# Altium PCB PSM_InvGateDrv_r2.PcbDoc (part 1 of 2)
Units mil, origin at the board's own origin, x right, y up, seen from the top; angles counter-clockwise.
Board outline 5413.39 x 2000 mil, 2 copper layers (Top Layer, Bottom Layer), stack 62 mil thick; 132 components, 58 nets, 317 pads, 172 vias.
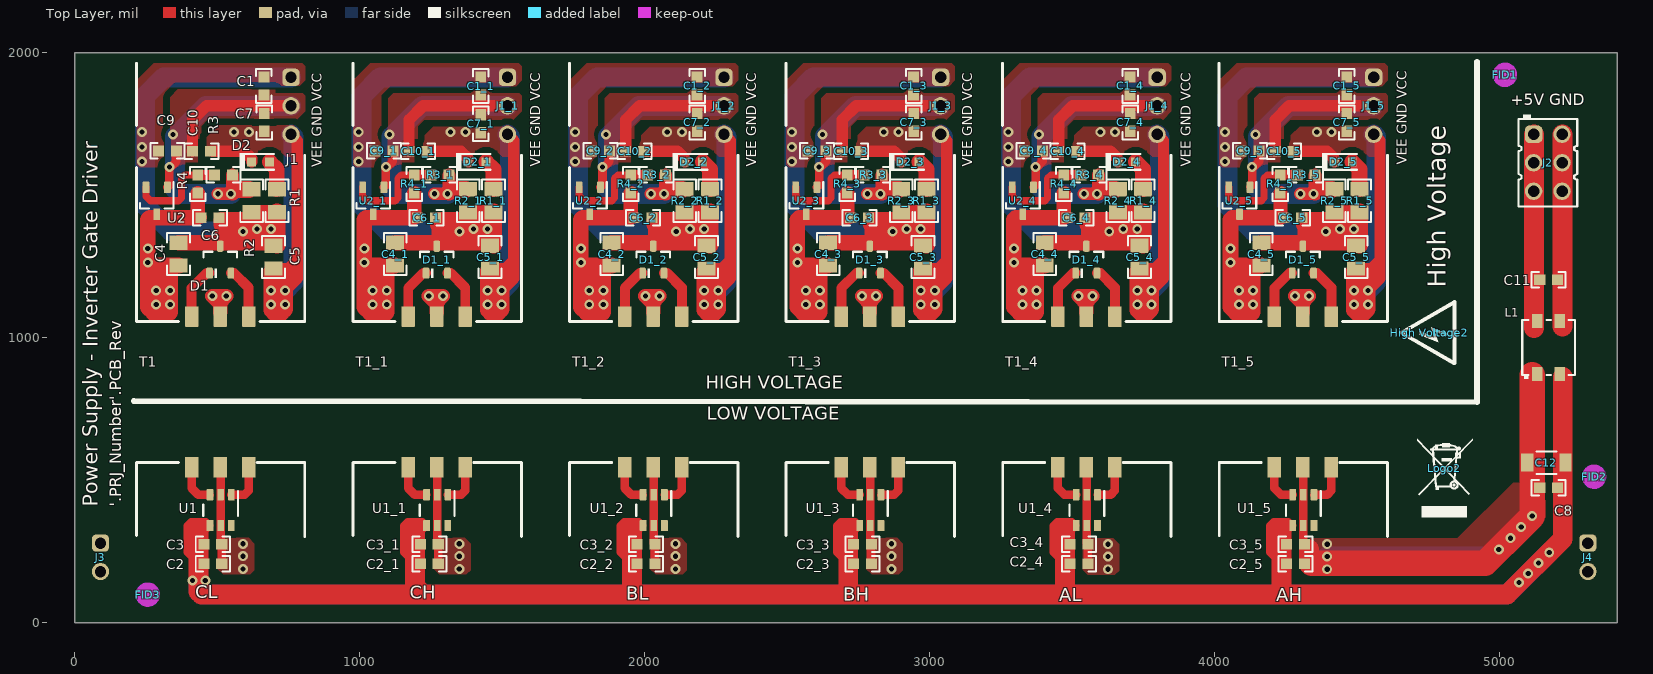
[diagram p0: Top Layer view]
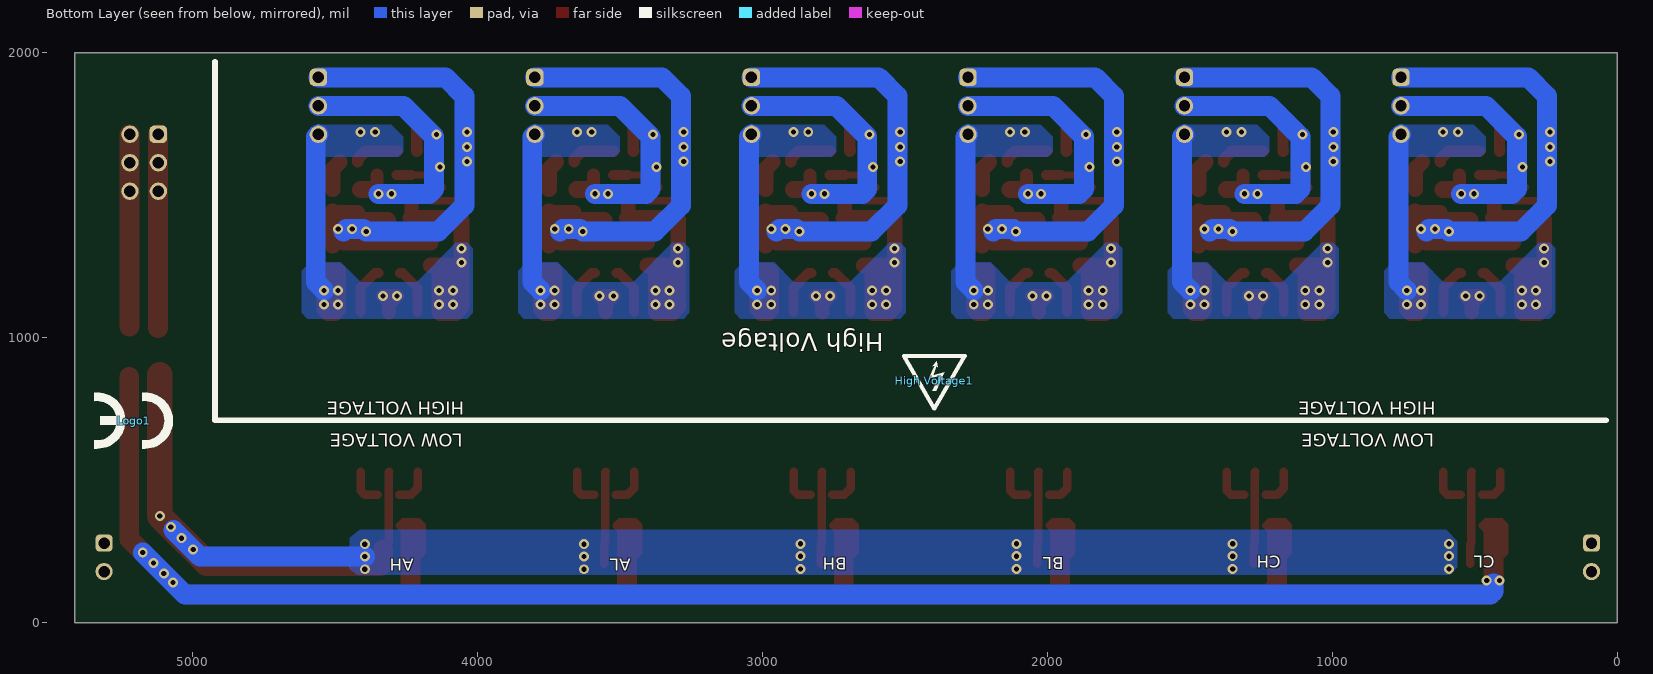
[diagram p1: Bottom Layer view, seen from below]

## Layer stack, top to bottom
Top Solder: solder mask 0.4, Solder Resist, Dk 3.5
Top Layer: signal copper 1.4
Dielectric1: core 59.2, FR-4, Dk 4.8
Bottom Layer: signal copper 1.4
Bottom Solder: solder mask 0.4, Solder Resist, Dk 3.5

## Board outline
0,0 5413.39,0 5413.39,2000 0,2000

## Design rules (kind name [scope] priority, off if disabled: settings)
AcuteAngle [All] p1: minimum=4.50000000000000E+0001 checktracksonly=FALSE
AssemblyTestPointUsage [All] p1: valid=2
BoardOutlineClearance BoardOutlineClearance_MountingHoles [OnCopper and InComponentClass('Mounting Holes')] p1: gap=20 ignorepadtopadclearanceinfootprint=FALSE
BoardOutlineClearance BoardOutlineClearance_Poly [OnCopper and IsPoly] p2: gap=25 ignorepadtopadclearanceinfootprint=FALSE
BoardOutlineClearance [OnCopper and Not InComponentClass('Logo') and not InComponentClass('FiducialMark') and not InRegion(1000,500,4000,800) and not InPoly] p3: gap=20 ignorepadtopadclearanceinfootprint=FALSE
Clearance Clearance_Keepouts [((IsTrack Or IsArc) And Not InPoly) And IsFree and IsKeepOut vs ((IsTrack Or IsArc) And Not InPoly) And IsFree and IsKeepOut] p1: gap=0 ignorepadtopadclearanceinfootprint=FALSE
Clearance Clearance_Poly [InPolygon] p2: gap=25 ignorepadtopadclearanceinfootprint=TRUE
Clearance Clearance_FiducialMark [IsKeepOut and InComponentClass('FiducialMark') vs IsPad and InComponentClass('FiducialMark')] p3: gap=0 ignorepadtopadclearanceinfootprint=FALSE
Clearance [All] p4: gap=7.87 ignorepadtopadclearanceinfootprint=TRUE
ComponentClearance ComponentClearance_MountingHoles_FiducialMarks [InComponentClass('Mounting Holes') vs InComponentClass('FiducialMark')] p1: gap=50 collisioncheckmode=3 verticalgap=10 showdistances=FALSE
ComponentClearance ComponentClearance_Shunt [InComponentClass('Header') vs InComponentClass('Shunt')] p2: gap=0 collisioncheckmode=3 verticalgap=0 showdistances=FALSE
ComponentClearance ComponentClearance_Logo [InComponentClass('Logo')] p3: gap=50 collisioncheckmode=3 verticalgap=10 showdistances=FALSE
ComponentClearance ComponentClearance_ScrewToNut [(HasFootprint('NY PMS 440 0025 PH')) vs (HasFootprint('Keystone_1902C'))] p4: gap=5 collisioncheckmode=3 verticalgap=10 showdistances=FALSE
ComponentClearance ComponentClearance_MountingHoles [InComponentClass('Mounting Holes')] p5: gap=250 collisioncheckmode=3 verticalgap=100000 showdistances=FALSE
ComponentClearance ComponentClearance_SmallPassives [HasFootprint('0201*') or HasFootprint('0402*') or HasFootprint('0508') or HasFootprint('0603*') or HasFootprint('0612') or HasFootprint('0805*') or HasFootprint('0815*') or HasFootprint('0830*') or HasFootprint('1206*') or HasFootprint('1210*') or HasFootprint('1808*') or HasFootprint('1812*') or HasFootprint('1825*') or HasFootprint('2010*') or HasFootprint('2220*') or HasFootprint('2225*') or HasFootprint('2512*') or HasFootprint('2728*') or HasFootprint('3518*') vs HasFootprint('0201*') or HasFootprint('0402*') or HasFootprint('0508') or HasFootprint('0603*') or HasFootprint('0612') or HasFootprint('0805*') or HasFootprint('0815*') or HasFootprint('0830*') or HasFootprint('1206*') or HasFootprint('1210*') or HasFootprint('1808*') or HasFootprint('1812*') or HasFootprint('1825*') or HasFootprint('2010*') or HasFootprint('2220*') or HasFootprint('2225*') or HasFootprint('2512*') or HasFootprint('2728*') or HasFootprint('3518*')] p6: gap=14.96 collisioncheckmode=3 verticalgap=10 showdistances=FALSE
ComponentClearance ComponentClearance_THtoSMT [IsThruComponent vs IsSMTComponent] p7: gap=25 collisioncheckmode=3 verticalgap=30 showdistances=FALSE
ComponentClearance ComponentClearance_THtoTH [IsThruComponent vs IsThruComponent] p8: gap=30 collisioncheckmode=3 verticalgap=30 showdistances=FALSE
ComponentClearance [All] p9: gap=30 collisioncheckmode=3 verticalgap=10 showdistances=FALSE
DiffPairsRouting [All] p1: maxlimit=100 minlimit=10 mostfreqgap=10 toplayer_minwidth=15 toplayer_maxwidth=15 toplayer_prefwidth=15 bottomlayer_minwidth=15 bottomlayer_maxwidth=15 bottomlayer_prefwidth=15 maxuncoupledlength=1000
FabricationTestPointUsage TestPointUsage [All] p1: valid=2 allowmultiple=FALSE
FabricationTestpoint Testpoint [All] p1: side=3 testpointundercomponent=TRUE minsize=40 maxsize=100 preferedsize=60 minholesize=0 maxholesize=40 preferedholesize=32 testpointgrid=1 allowsidetop=TRUE allowsidebottom=TRUE usegrid=TRUE gridtolerance=0.01
FanoutControl Fanout_LCC [IsLCC] p1: bgadir=Out bgaviamode=Centered fanoutstyle=Auto fanoutdirection=Alternating viagrid=1 // Fanout_LCC (Default Rule)
FanoutControl Fanout_BGA [IsBGA] p2: bgadir=Out bgaviamode=Centered fanoutstyle=Auto fanoutdirection=Alternating viagrid=1 // Fanout_BGA (Default Rule)
FanoutControl Fanout_Default [All] p4: bgadir=Out bgaviamode=Centered fanoutstyle=Auto fanoutdirection=Alternating viagrid=1 // Fanout_Default (Default Rule)
FanoutControl Fanout_Small [(CompPinCount < 5)] p5: bgadir=Out bgaviamode=Centered fanoutstyle=Auto fanoutdirection=OutThenIn viagrid=1 // Fanout_Small (Default Rule)
HoleSize [All] p1: absolutevalues=TRUE maxlimit=251 minlimit=7.87 maxpercent=80.000 minpercent=20.000
MinimumAnnularRing MinimumAnnularRing_ThermalPadVias [IsVia and InAnyComponent] p1: minimumring=5.91
MinimumAnnularRing [All] p2: minimumring=7.87
MinimumSolderMaskSliver MinimumSolderMaskSliver_Logo [InComponentClass('Logo') vs InComponentClass('Logo')] p1: minsoldermaskwidth=0.7
MinimumSolderMaskSliver [All] p2: minsoldermaskwidth=3.94
PlaneConnect [All] p1: planeconnectstyle=Relief reliefexpansion=10 reliefentries=4 reliefconductorwidth=10 reliefairgap=10
PolygonConnect [All] p1: connectstyle=Direct reliefconductorwidth=10 reliefentries=4 polygonreliefangle="90 Angle" airgapwidth=10
RoomDefinition "Bias Supply_4" [InComponentClass('Bias Supply')] p1: confinementstyle=ConfineIn formatcopy=TRUE lockcomponents=FALSE outline 4615.87,368.9 4615.87,1765.5 4015.87,1765.5 4015.87,368.9
RoomDefinition "Bias Supply_3" [InComponentClass('Bias Supply')] p2: confinementstyle=ConfineIn formatcopy=TRUE lockcomponents=FALSE outline 3855.87,368.9 3855.87,1765.5 3255.87,1765.5 3255.87,368.9
RoomDefinition PSM_InvGateDrv [InComponentClass('PSM_InvGateDrv')] p3: confinementstyle=ConfineIn formatcopy=TRUE lockcomponents=FALSE outline 3095.87,368.9 3095.87,1765.5 2495.87,1765.5 2495.87,368.9
RoomDefinition "Bias Supply_1" [InComponentClass('Bias Supply')] p4: confinementstyle=ConfineIn formatcopy=TRUE lockcomponents=FALSE outline 2335.87,368.9 2335.87,1765.5 1735.87,1765.5 1735.87,368.9
RoomDefinition 1 [InComponentClass('1')] p5: confinementstyle=ConfineIn formatcopy=TRUE lockcomponents=FALSE outline 4615.87,368.9 4615.87,1765.5 4015.87,1765.5 4015.87,368.9
RoomDefinition 2 [InComponentClass('2')] p6: confinementstyle=ConfineIn formatcopy=TRUE lockcomponents=FALSE outline 3855.87,368.9 3855.87,1765.5 3255.87,1765.5 3255.87,368.9
RoomDefinition 3 [InComponentClass('3')] p7: confinementstyle=ConfineIn formatcopy=TRUE lockcomponents=FALSE outline 3095.87,368.9 3095.87,1765.5 2495.87,1765.5 2495.87,368.9
RoomDefinition "Stark Gate Driver_1" [InComponentClass('Stark Gate Driver_1')] p8: confinementstyle=ConfineIn formatcopy=TRUE lockcomponents=FALSE outline 2335.87,368.9 2335.87,1765.5 1735.87,1765.5 1735.87,368.9
RoomDefinition "Bias Supply" [InComponentClass('Bias Supply')] p9: confinementstyle=ConfineIn formatcopy=TRUE lockcomponents=FALSE outline 815.87,368.9 815.87,1949.29 215.87,1949.29 215.87,368.9
RoomDefinition 5 [InComponentClass('5')] p10: confinementstyle=ConfineIn formatcopy=TRUE lockcomponents=FALSE outline 1575.87,368.9 1575.87,1765.5 975.87,1765.5 975.87,368.9
RoutingVias ThermalPadVias [IsVia and InAnyComponent] p1: holewidth=7.87 width=19.68 viastyle="Through Hole" minholewidth=7.87 minwidth=19.68 maxholewidth=12.99 maxwidth=23.62
RoutingVias [All] p2: holewidth=16 width=34 viastyle="Through Hole" minholewidth=7.87 minwidth=26 maxholewidth=40 maxwidth=65
SilkToBoardRegionClearance [Not ((IsComment or IsDesignator) And (Hide <> 'False')) and not InRegion(1000,500,4000,800)] p1:
SilkToSilkClearance SilkToSilkClearance_Pb-FreeLogo [(HasFootprint('Pb-Free_Overlay_Medium') OR HasFootprint('Pb-Free_Overlay_Small')) vs (HasFootprint('Pb-Free_Overlay_Medium') OR HasFootprint('Pb-Free_Overlay_Small'))] p1: silktosilkclearance=0
SilkToSilkClearance [All] p2: silktosilkclearance=2
SilkToSolderMaskClearance SilkToComponentPadClearance [(IsPad or IsFill or IsRegion) and InAnycomponent] p1: minsilkscreentomaskgap=0 clearancetoexposedcopper=TRUE
SilkToSolderMaskClearance "Silk to Solder Mask Opening" [All] p2: minsilkscreentomaskgap=1 clearancetoexposedcopper=FALSE
SolderMaskExpansion [All] p1: expansion=1.97
UnRoutedNet [All] p1: checkbadconnections=TRUE
Width [All] p1: maxlimit=100 minlimit=6 preferedwidth=10 checkconnectedcopper=TRUE
14 further rules are at their usual default settings.

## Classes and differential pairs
component class Header: J1 J1_1 J1_2 J1_3 J1_4 J1_5 J2 J3 J4
component class FiducialMark: FID1 FID2 FID3
component class AssemblyNote: ZZ1 ZZ2 ZZ3 ZZ4

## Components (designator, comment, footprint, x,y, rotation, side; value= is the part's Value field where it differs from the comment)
C1 "CGA3E2X7R1E104K080AA" 0603 663.75,1883.91 r270 top value=0.1uF
C1_1 "CGA3E2X7R1E104K080AA" 0603 1424.5,1883.54 r270 top value=0.1uF
C1_2 "CGA3E2X7R1E104K080AA" 0603 2183.75,1883.91 r270 top value=0.1uF
C1_3 "CGA3E2X7R1E104K080AA" 0603 2943.75,1883.91 r270 top value=0.1uF
C1_4 "CGA3E2X7R1E104K080AA" 0603 3703.75,1883.91 r270 top value=0.1uF
C1_5 "CGA3E2X7R1E104K080AA" 0603 4463.75,1883.91 r270 top value=0.1uF
C2 "GRT188C81A106ME13D" 0603 484.38,206.52 r180 top value=10uF
C2_1 "GRT188C81A106ME13D" 0603 1244.38,206.52 r180 top value=10uF
C2_2 "GRT188C81A106ME13D" 0603 2004.38,206.52 r180 top value=10uF
C2_3 "GRT188C81A106ME13D" 0603 2764.38,206.52 r180 top value=10uF
C2_4 "GRT188C81A106ME13D" 0603 3524.38,206.52 r180 top value=10uF
C2_5 "GRT188C81A106ME13D" 0603 4284.38,206.52 r180 top value=10uF
C3 "CGA3E2X7R1E104K080AA" 0603 484.38,275.42 r180 top value=0.1uF
C3_1 "CGA3E2X7R1E104K080AA" 0603 1244.38,275.42 r180 top value=0.1uF
C3_2 "CGA3E2X7R1E104K080AA" 0603 2004.38,275.42 r180 top value=0.1uF
C3_3 "CGA3E2X7R1E104K080AA" 0603 2764.38,275.42 r180 top value=0.1uF
C3_4 "CGA3E2X7R1E104K080AA" 0603 3524.38,275.42 r180 top value=0.1uF
C3_5 "CGA3E2X7R1E104K080AA" 0603 4284.38,275.42 r180 top value=0.1uF
C4 "GRT21BR61H475KE13L" 0805_HV 364.3,1293.78 r270 top value=4.7uF
C4_1 "GRT21BR61H475KE13L" 0805_HV 1124.3,1293.78 r270 top value=4.7uF
C4_2 "GRT21BR61H475KE13L" 0805_HV 1884.3,1293.78 r270 top value=4.7uF
C4_3 "GRT21BR61H475KE13L" 0805_HV 2644.3,1293.78 r270 top value=4.7uF
C4_4 "GRT21BR61H475KE13L" 0805_HV 3404.3,1293.78 r270 top value=4.7uF
C4_5 "GRT21BR61H475KE13L" 0805_HV 4164.3,1293.78 r270 top value=4.7uF
C5 "GRT21BR61H475KE13L" 0805_HV 697.3,1283.15 r270 top value=4.7uF
C5_1 "GRT21BR61H475KE13L" 0805_HV 1457.3,1283.15 r270 top value=4.7uF
C5_2 "GRT21BR61H475KE13L" 0805_HV 2217.3,1283.15 r270 top value=4.7uF
C5_3 "GRT21BR61H475KE13L" 0805_HV 2977.3,1283.15 r270 top value=4.7uF
C5_4 "GRT21BR61H475KE13L" 0805_HV 3737.3,1283.15 r270 top value=4.7uF
C5_5 "GRT21BR61H475KE13L" 0805_HV 4497.3,1283.15 r270 top value=4.7uF
C6 "CGA3E2X7R1E104K080AA" 0603 474.54,1421.73 r180 top value=0.1uF
C6_1 "CGA3E2X7R1E104K080AA" 0603 1234.54,1421.73 r180 top value=0.1uF
C6_2 "CGA3E2X7R1E104K080AA" 0603 1994.54,1421.73 r180 top value=0.1uF
C6_3 "CGA3E2X7R1E104K080AA" 0603 2754.54,1421.73 r180 top value=0.1uF
C6_4 "CGA3E2X7R1E104K080AA" 0603 3514.54,1421.73 r180 top value=0.1uF
C6_5 "CGA3E2X7R1E104K080AA" 0603 4274.54,1421.73 r180 top value=0.1uF
C7 "CGA3E2X7R1E104K080AA" 0603 664.5,1755.96 r270 top value=0.1uF
C7_1 "CGA3E2X7R1E104K080AA" 0603 1424.5,1750.96 r270 top value=0.1uF
C7_2 "CGA3E2X7R1E104K080AA" 0603 2184.5,1755.96 r270 top value=0.1uF
C7_3 "CGA3E2X7R1E104K080AA" 0603 2944.5,1755.96 r270 top value=0.1uF
C7_4 "CGA3E2X7R1E104K080AA" 0603 3704.5,1755.96 r270 top value=0.1uF
C7_5 "CGA3E2X7R1E104K080AA" 0603 4464.5,1755.96 r270 top value=0.1uF
C8 "CGA3E2X7R1E104K080AA" 0603 5172.8,472.91 r0 top value=0.1uF
C9 "CGA3E2X7R1E104K080AA" 0603 324.93,1655.54 r0 top value=0.1uF
C9_1 "CGA3E2X7R1E104K080AA" 0603 1084.93,1655.54 r0 top value=0.1uF
C9_2 "CGA3E2X7R1E104K080AA" 0603 1844.93,1655.54 r0 top value=0.1uF
C9_3 "CGA3E2X7R1E104K080AA" 0603 2604.93,1655.54 r0 top value=0.1uF
C9_4 "CGA3E2X7R1E104K080AA" 0603 3364.93,1655.54 r0 top value=0.1uF
C9_5 "CGA3E2X7R1E104K080AA" 0603 4124.93,1655.54 r0 top value=0.1uF
C10 "CGA3E2X7R1E104K080AA" 0603 444.52,1654.55 r0 top value=0.1uF
C10_1 "CGA3E2X7R1E104K080AA" 0603 1204.52,1654.55 r0 top value=0.1uF
C10_2 "CGA3E2X7R1E104K080AA" 0603 1964.52,1654.55 r0 top value=0.1uF
C10_3 "CGA3E2X7R1E104K080AA" 0603 2724.52,1654.55 r0 top value=0.1uF
C10_4 "CGA3E2X7R1E104K080AA" 0603 3484.52,1654.55 r0 top value=0.1uF
C10_5 "CGA3E2X7R1E104K080AA" 0603 4244.52,1654.55 r0 top value=0.1uF
C11 "GRT188R61C475KE13D" 0603 5172.8,1203.03 r0 top value=4.7uF
C12 "GRJ31CR71A226KE12L" 1206_190 5164.92,561.5 r0 top value=22uF
D1 "BAV70-E3-08" SOT-23 510.26,1274.09 r90 top value=70V
D1_1 "BAV70-E3-08" SOT-23 1270.26,1274.09 r90 top value=70V
D1_2 "BAV70-E3-08" SOT-23 2030.26,1274.09 r90 top value=70V
D1_3 "BAV70-E3-08" SOT-23 2790.26,1274.09 r90 top value=70V
D1_4 "BAV70-E3-08" SOT-23 3550.26,1274.09 r90 top value=70V
D1_5 "BAV70-E3-08" SOT-23 4310.26,1274.09 r90 top value=70V
D2 "150060GS75000" WL-SMCW_GREEN 652.09,1617.15 r0 top value=Green
D2_1 "150060GS75000" WL-SMCW_GREEN 1412.09,1617.15 r0 top value=Green
D2_2 "150060GS75000" WL-SMCW_GREEN 2172.09,1617.15 r0 top value=Green
D2_3 "150060GS75000" WL-SMCW_GREEN 2932.09,1617.15 r0 top value=Green
D2_4 "150060GS75000" WL-SMCW_GREEN 3692.09,1617.15 r0 top value=Green
D2_5 "150060GS75000" WL-SMCW_GREEN 4452.09,1617.15 r0 top value=Green
FID1 "Fiducial" Fiducial10-20 5019.69,1922.91 r0 top
FID2 "Fiducial" Fiducial10-20 5332.48,512.28 r0 top
FID3 "Fiducial" Fiducial10-20 256.03,98.41 r0 top
"High Voltage1" "DANGER HIGH VOLTAGE" IEC_HighVoltage_Small 2396.62,848.5 r0 bottom
"High Voltage2" "DANGER HIGH VOLTAGE" IEC_HighVoltage_Small 4753.94,1018.29 r90 top
J1 "TSW-103-07-G-S" TSW-103-07-G-S 758.63,1814 r270 top
J1_1 "TSW-103-07-G-S" TSW-103-07-G-S 1518.63,1814 r270 top
J1_2 "TSW-103-07-G-S" TSW-103-07-G-S 2278.63,1814 r270 top
J1_3 "TSW-103-07-G-S" TSW-103-07-G-S 3038.63,1814 r270 top
J1_4 "TSW-103-07-G-S" TSW-103-07-G-S 3798.63,1814 r270 top
J1_5 "TSW-103-07-G-S" TSW-103-07-G-S 4558.63,1814 r270 top
J2 "HTSW-103-07-G-D" Samtec_HTSW-103-07-x-D 5170.2,1614.27 r0 top
J3 "TSW-102-23-T-S" Samtec_TSW-102-23-X-S 90,229.27 r270 top
J4 "TSW-102-23-T-S" Samtec_TSW-102-23-X-S 5310.8,229.27 r270 top
L1 "ACM4520V-142-2P-T00" TDK_ACM4520 5172.8,965.83 r90 top
Logo1 "CE Mark" CE_Mark_5mm 5206.8,709.13 r0 bottom
Logo2 "WEEE logo" WEEE_Minimum 4806.94,541.45 r0 top
R1 "CRCW080519K1FKEA" 0805_HV 709.18,1480.79 r270 top value=19.1k
R1_1 "CRCW080519K1FKEA" 0805_HV 1469.18,1480.79 r270 top value=19.1k
R1_2 "CRCW080519K1FKEA" 0805_HV 2229.18,1480.79 r270 top value=19.1k
R1_3 "CRCW080519K1FKEA" 0805_HV 2989.18,1480.79 r270 top value=19.1k
R1_4 "CRCW080519K1FKEA" 0805_HV 3749.18,1480.79 r270 top value=19.1k
R1_5 "CRCW080519K1FKEA" 0805_HV 4509.18,1480.79 r270 top value=19.1k
R2 "ERJ-P06F4701V" 0805_HV 620.6,1480.79 r270 top value=4.70k
R2_1 "ERJ-P06F4701V" 0805_HV 1380.6,1480.79 r270 top value=4.70k
R2_2 "ERJ-P06F4701V" 0805_HV 2140.6,1480.79 r270 top value=4.70k
R2_3 "ERJ-P06F4701V" 0805_HV 2900.6,1480.79 r270 top value=4.70k
R2_4 "ERJ-P06F4701V" 0805_HV 3660.6,1480.79 r270 top value=4.70k
R2_5 "ERJ-P06F4701V" 0805_HV 4420.6,1480.79 r270 top value=4.70k
R3 "RT0603DRE073K01L" 0603 521.78,1571.34 r0 top value=3.01k
R3_1 "RT0603DRE073K01L" 0603 1281.78,1571.34 r0 top value=3.01k
R3_2 "RT0603DRE073K01L" 0603 2041.78,1571.34 r0 top value=3.01k
R3_3 "RT0603DRE073K01L" 0603 2801.78,1571.34 r0 top value=3.01k
R3_4 "RT0603DRE073K01L" 0603 3561.78,1571.34 r0 top value=3.01k
R3_5 "RT0603DRE073K01L" 0603 4321.78,1571.34 r0 top value=3.01k
R4 "RT0603DRE074K99L" 0603 431.33,1539.84 r90 top value=4.99k
R4_1 "RT0603DRE074K99L" 0603 1191.33,1539.84 r90 top value=4.99k
R4_2 "RT0603DRE074K99L" 0603 1951.33,1539.84 r90 top value=4.99k
R4_3 "RT0603DRE074K99L" 0603 2711.33,1539.84 r90 top value=4.99k
R4_4 "RT0603DRE074K99L" 0603 3471.33,1539.84 r90 top value=4.99k
R4_5 "RT0603DRE074K99L" 0603 4231.33,1539.84 r90 top value=4.99k
T1 "750316856" Wurth_750316856 510.26,809.92 r90 top value=200uH
T1_1 "750316856" Wurth_750316856 1270.26,809.92 r90 top value=200uH
T1_2 "750316856" Wurth_750316856 2030.26,809.92 r90 top value=200uH
T1_3 "750316856" Wurth_750316856 2790.26,809.92 r90 top value=200uH
T1_4 "750316856" Wurth_750316856 3550.26,809.92 r90 top value=200uH
T1_5 "750316856" Wurth_750316856 4310.26,809.92 r90 top value=200uH
U1 "SN6505DQDBVRQ1" DBV0006A_N 511.94,394.96 r270 top
U1_1 "SN6505DQDBVRQ1" DBV0006A_N 1271.94,394.96 r270 top
U1_2 "SN6505DQDBVRQ1" DBV0006A_N 2031.94,394.96 r270 top
U1_3 "SN6505DQDBVRQ1" DBV0006A_N 2791.94,394.96 r270 top
U1_4 "SN6505DQDBVRQ1" DBV0006A_N 3551.94,394.96 r270 top
U1_5 "SN6505DQDBVRQ1" DBV0006A_N 4311.94,394.96 r270 top
U2 "TL431AQDBZRQ1" DBZ0003A_N 287.53,1480.79 r270 top
U2_1 "TL431AQDBZRQ1" DBZ0003A_N 1047.53,1480.79 r270 top
U2_2 "TL431AQDBZRQ1" DBZ0003A_N 1807.53,1480.79 r270 top
U2_3 "TL431AQDBZRQ1" DBZ0003A_N 2567.53,1480.79 r270 top
U2_4 "TL431AQDBZRQ1" DBZ0003A_N 3327.53,1480.79 r270 top
U2_5 "TL431AQDBZRQ1" DBZ0003A_N 4087.53,1480.79 r270 top
ZZ1 "This Assembly Note is for PCB labels only" AssemblyNoteLabel 185,3946.41 r0 top
ZZ2 "These assemblies are ESD sensitive, ESD precautions shall be observed." AssemblyNote 187.81,3849.33 r0 top
ZZ3 "These assemblies must be clean and free from flux and all contaminants. Use of no clean flux is not acceptable." AssemblyNote 187.81,3760.78 r0 top
ZZ4 "These assemblies must comply with workmanship standards IPC-A-610 Class 2, unless otherwise specified." AssemblyNote 187.81,3672.22 r0 top

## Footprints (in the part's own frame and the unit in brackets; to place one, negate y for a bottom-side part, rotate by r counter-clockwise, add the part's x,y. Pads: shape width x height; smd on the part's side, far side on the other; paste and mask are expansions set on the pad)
0603 [mm] "0603 from SM-752 data"
  rect 1x0.95 smd: 1(-0.8,0) 2(0.8,0)
  silkscreen extent -1.52,-0.69 1.52,0.69, body extent -0.87,-0.47 0.87,0.47, height 1
0805_HV [mil] "0805 with 30mil clearance between pads"
  rect 50x63 smd: 1(-40,0) 2(40,0)
  silkscreen extent -74,-40 74,40, body extent -43,-29 43,29, height 57
1206_190 [mm] "1206_190"
  rect 1.1x1.6 smd: 1(-1.7,0) 2(1.7,0)
  silkscreen extent -0.9,-1 0.9,1, body extent -1.75,-0.95 1.75,0.95, height 1.9
AssemblyNote [mil] "Assembly Note"
AssemblyNoteLabel [mil] "Assembly Note for PCB Labels"
CE_Mark_5mm [mil] "Minimum text height for CE Mark"
  silkscreen extent -138,-98 138,98
DBV0006A_N [mm] "SOT23, 6-Leads, Body 2.9x1.6mm, Pitch 0.95mm, Lead Span 2.8mm, IPC Medium Density"
  rrect17% 1x0.6 smd: 1(-1.375,0.95) 2(-1.375,0) 3(-1.375,-0.95) 4(1.375,-0.95) 5(1.375,0) 6(1.375,0.95)
  silkscreen extent -1.68,-1.55 0.5,1.55, body extent -1.42,-1.46 1.42,1.46, height 1.12
DBZ0003A_N [mm] "SOT23, 3-Leads, Body 2.9x1.3mm, Pitch 0.95mm, Lead Span 2.4mm, IPC Medium Density"
  rrect17% 1x0.6 smd: 1(-1.2,0.95) 2(-1.2,-0.95) 3(1.2,0)
  silkscreen extent -1.65,-1.5 0.7,1.5, body extent -1.26,-1.46 1.26,1.46, height 0.98
Fiducial10-20 [mm]
  round 1 smd mask+0.5: 1(0,0)
  Top Layer keep-out circle w1.178: c0,0 r0.5
IEC_HighVoltage_Small [mil]
  silkscreen extent -107,-88 107,97
Samtec_HTSW-103-07-x-D [mm] "Header, 2.54mm, 3x2, Gold, TH"
  rrect50% 1.55x1.55 hole 1.02: 1(-1.27,2.54)
  round 1.55 hole 1.02: 2(1.27,2.54) 3(-1.27,0) 4(1.27,0) 5(-1.27,-2.54) 6(1.27,-2.54)
  silkscreen extent -2.61,-3.91 2.61,4.3, body extent -2.51,-3.81 2.51,3.81, height 8.38
Samtec_TSW-102-23-X-S [mm] "Header, 2.54mm, 2x1, TH"
  rrect50% 1.53x1.53 hole 1.02: 1(-1.27,0)
  round 1.53 hole 1.02: 2(1.27,0)
  body extent -2.67,-1.27 2.54,1.27, height 8.38
SOT-23 [mm] "SOT23, 3-Leads, Body 2.9x1.3mm, Pitch 0.95mm, Lead Span 2.5mm, IPC Medium Density"
  rrect50% 1x0.6 smd: 1(-1.2,0.95) 2(-1.2,-0.95) 3(1.2,0)
  silkscreen extent -1.62,-1.5 0.7,1.5, body extent -1.16,-1.45 1.21,1.45, height 1
TDK_ACM4520 [mm] "SMD, 4-Leads, Body 4.7x4.5mm"
  rect 1.25x0.95 smd: 1(-2.375,1) 2(-2.375,-1) 3(2.375,-1) 4(2.375,1)
  silkscreen extent -2.8,-2.35 2.45,2.35, body extent -2.45,-2.35 2.45,2.35, height 2
TSW-103-07-G-S [mil] "Samtec 100mil, 1x3, 230 mil above insulator"
  rrect50% 61x61 hole 40: 1(-100,0)
  round 61 hole 40: 2(0,0) 3(100,0)
  body extent -150,-50 150,50, height 330
WEEE_Minimum [mil] "WEEElie bin"
  silkscreen extent -95,-172 99,104
WL-SMCW_GREEN [mm] "WURTH"
  rect 0.8x0.8 smd: 1(-0.8,0) 2(0.8,0)
  silkscreen extent -1.9,-0.8 1.2,0.8, body extent -0.85,-0.45 0.85,0.45, height 0.8
Wurth_750316856 [mm] "SMD, 6-Leads, Body 11.43x8.3mm, Pitch 2.54mm"
  rrect8% 1.82x1.22 smd: 1(-6.715,2.54) 2(-6.715,0) 3(-6.715,-2.54) 4(6.715,-2.54) 5(6.715,0) 6(6.715,2.54)
  body extent -7.12,-4.02 7.12,4.01, height 4.09

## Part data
C1 C1_1 C1_2 C1_3 C1_4 C1_5 C3 C3_1 C3_2 C3_3 C3_4 C3_5 C6 C6_1 C6_2 C6_3 C6_4 C6_5 C7 C7_1 C7_2 C7_3 C7_4 C7_5 C8 C9 C9_1 C9_2 C9_3 C9_4 C9_5 C10 C10_1 C10_2 C10_3 C10_4 C10_5: "CAP, CERM, 0.1 µF, 25 V,+/- 10%, X7R, AEC-Q200 Grade 1, 0603", Cap_Case=0603, Manufacturer=TDK, Supplier Part Number 1=445-5667-1-ND, TempCo=X7R, Tolerance_%=10, Value2=25V, ValueDisplayed=0.1µF
C2 C2_1 C2_2 C2_3 C2_4 C2_5: "CAP, CERM, 10 µF, 10 V,+/- 20%, X6S, AEC-Q200 Grade 2, 0603", Cap_Case=0603, Manufacturer=MuRata, Supplier Part Number 1=490-12283-1-ND, TempCo=X6S, Tolerance_%=20, Value2=10V, ValueDisplayed=10µF
C4 C4_1 C4_2 C4_3 C4_4 C4_5 C5 C5_1 C5_2 C5_3 C5_4 C5_5: "CAP, CERM, 4.7 µF, 50 V,+/- 10%, X5R, AEC-Q200 Grade 3, 0805", Cap_Case=0805, Manufacturer=MuRata, Supplier Part Number 1=490-12394-1-ND, TempCo=X5R, Tolerance_%=10, Value2=50V, ValueDisplayed=4.7µF
C11: library part CMP-0081052-1, "CAP, CERM, 4.7 µF, 16 V,+/- 10%, X5R, AEC-Q200 Grade 3, 0603", Cap_Case=0603, Manufacturer=MuRata, Supplier Part Number 1=490-12319-1-ND, TempCo=X5R, Tolerance_%=10%, Value2=16V, ValueDisplayed=4.7µF
C12: library part CMP-0074691-1, "CAP, CERM, 22 µF, 10 V,+/- 10%, X7R, 1206", Cap_Case=1206, Manufacturer=MuRata, Supplier Part Number 1=490-10937-1-ND, TempCo=X7R, Tolerance_%=10%, Value2=10V, ValueDisplayed=22µF
D1 D1_1 D1_2 D1_3 D1_4 D1_5: "Diode, Switching, 70 V, 0.25 A, AEC-Q101, SOT-23", Manufacturer=Vishay-Semiconductor, Supplier Part Number 1=BAV70-E3-08CT-ND, Value1=0.25A, Value2=1.25V
D2 D2_1 D2_2 D2_3 D2_4 D2_5: library part CMP-0002905-2, "LED, Green, SMD", Color=Green, Manufacturer="Wurth Elektronik", Value1=W, Value2=3.2V
FID1 FID2 FID3: library part CMP-0077181-1, "Fiducial mark.  There is nothing to buy or mount.", Manufacturer=N/A
"High Voltage1" "High Voltage2": library part CMP-0074835-1, "IEC 61010-1 High Voltage Warning"
J1 J1_1 J1_2 J1_3 J1_4 J1_5: library part CMP-0075407-2, "Header, 100mil, 3x1, Gold, TH", Color=Black, Current_A=6.3A, Manufacturer=Samtec, Supplier Part Number 1=SAM1029-03-ND, Voltage_V=550V
J2: library part CMP-0055587-2, "Header, 2.54mm, 3x2, Gold, TH", Color=Natural, Manufacturer=Samtec, Supplier Part Number 1=HTSW-103-07-G-D-ND
J3 J4: library part CMP-0084558-1, "Header, 2.54mm, 2x1, Tin, TH", Color=Black, Current_A=6.3A, Manufacturer=Samtec, Voltage_V=550V
L1: library part CMP-0084502-1, "Coupled inductor,  ohm, AEC-Q200 Grade 1, SMD", Manufacturer=TDK
Logo1: library part CMP-0074844-1
Logo2: library part CMP-0074769-1
R1 R1_1 R1_2 R1_3 R1_4 R1_5: "RES, 19.1 k, 1%, 0.125 W, 0805", Manufacturer=Vishay-Dale, Power_W=0.125, Supplier Part Number 1=541-19.1KCCT-ND, TempCo="100 ppm/C", Tolerance_%=1, Value1=1%, Value2=0.125W, Value_Code=19k1, ValueDisplayed=19.1k
R2 R2_1 R2_2 R2_3 R2_4 R2_5: library part CMP-0021852-2, "RES, 4.70 k, 1%, 0.5 W, AEC-Q200 Grade 0, 0805", Manufacturer=Panasonic, Power_W=500mW, Supplier Part Number 1=P16073CT-ND, TempCo="100 ppm/C", Tolerance_%=1%, Value2=0.5W, Value_Code=4k70, ValueDisplayed=4.70k
R3 R3_1 R3_2 R3_3 R3_4 R3_5: "RES, 3.01 k, 0.5%, 0.1 W, 0603", Manufacturer="Yageo America", Power_W=0.1, TempCo="50 ppm/C", Tolerance_%=0.5, Value1=0.5%, Value2=0.1W, Value_Code=3k01, ValueDisplayed=3.01k
R4 R4_1 R4_2 R4_3 R4_4 R4_5: "RES, 4.99 k, 0.5%, 0.1 W, 0603", Manufacturer="Yageo America", Power_W=0.1, TempCo="50 ppm/C", Tolerance_%=0.5, Value1=0.5%, Value2=0.1W, Value_Code=4k99, ValueDisplayed=4.99k
T1 T1_1 T1_2 T1_3 T1_4 T1_5: library part CMP-0081897-1, "Transformer, 200 uH, SMD", Manufacturer="Wurth Elektronik", ValueDisplayed=200µH
U1 U1_1 U1_2 U1_3 U1_4 U1_5: library part CMP-0860735-1, "SN6505DQDBVRQ1, DBV0006A (SOT-23-6)", Alternate Manufacturer="Texas Instruments", Alternate PartNumber=SN6505DQDBVTQ1
U2 U2_1 U2_2 U2_3 U2_4 U2_5: "Automotive Catalog Adjustable Precision Shunt Regulator, 34 ppm / degC, 100 mA, -40 to 125 degC, 3-pin SOT-23 (DBZ), Green (RoHS & no Sb/Br)", Alternate Manufacturer="Texas Instruments", Alternate PartNumber=Equivalent, Rating=Automotive, Supplier Part Number 1=296-21853-2-ND, Temp Coeff(Typ)(ppm/ degree C)=34
ZZ1: library part CMP-0003616-3
ZZ2: library part CMP-0077236-1
ZZ3: library part CMP-0077237-1
ZZ4: library part CMP-0077238-1

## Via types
v1: diameter 35, hole 18, Top Layer to Bottom Layer, 172 vias

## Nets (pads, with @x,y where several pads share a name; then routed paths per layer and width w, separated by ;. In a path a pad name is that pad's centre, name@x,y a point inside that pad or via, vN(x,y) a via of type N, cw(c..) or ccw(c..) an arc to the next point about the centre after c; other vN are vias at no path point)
5Vin: C11.1 J2.1 J2.3 J2.5 L1.4 | length 679.5
  Top Layer w70: 5120.8,1034.54 J2.1@5120.8,1714
5Vs: C2.1 C2_1.1 C2_2.1 C2_3.1 C2_4.1 C2_5.1 C3.1 C3_1.1 C3_2.1 C3_3.1 C3_4.1 C3_5.1 C8.1 C12.1 L1.1 T1.2 T1_1.2 T1_2.2 T1_3.2 T1_4.2 T1_5.2 U1.2 U1.5 U1_1.2 U1_1.5 U1_2.2 U1_2.5 U1_3.2 U1_3.5 U1_4.2 U1_4.5 U1_5.2 U1_5.5 | length 4047.4
  Top Layer w30: T1.2@510.26,530 511.94,528.33 U1.2@511.94,449.09 U1.5@511.94,340.83 511.94,279.35 C3.1@515.87,275.42 C2.1@515.87,206.52 ; T1_1.2@1270.26,530 1271.94,528.33 U1_1.2@1271.94,449.09 U1_1.5@1271.94,340.83 1271.94,279.35 C3_1.1@1275.87,275.42 C2_1.1@1275.87,206.52 ; T1_2.2@2030.26,530 2031.94,528.33 U1_2.2@2031.94,449.09 U1_2.5@2031.94,340.83 2031.94,279.35 C3_2.1@2035.87,275.42 C2_2.1@2035.87,206.52 ; T1_3.2@2790.26,530 2791.94,528.33 U1_3.2@2791.94,449.09 U1_3.5@2791.94,340.83 2791.94,279.35 C3_3.1@2795.87,275.42 C2_3.1@2795.87,206.52 ; T1_4.2@3550.26,530 3551.94,528.33 U1_4.2@3551.94,449.09 U1_4.5@3551.94,340.83 3551.94,279.35 C3_4.1@3555.87,275.42 C2_4.1@3555.87,206.52 ; T1_5.2@4310.26,530 4311.94,528.33 U1_5.2@4311.94,449.09 U1_5.5@4311.94,340.83 4311.94,279.35 C3_5.1@4315.87,275.42 C2_5.1@4315.87,206.52
  Top Layer w70: 4331.62,256.38 4331.62,219.22 4341.77,209.08
  Top Layer w90: 4341.77,209.08 4950.54,209.08 4968.31,226.85 v1(4997.83,256.38) 5027.36,285.91 5055.41,313.95 v1(5115.16,373.7) L1.1@5115.16,869.37
  Bottom Layer w70: v1(4395.6,231.85) 4968.31,231.85 ; 4974.79,231.85 v1@5067.47,324.54
  other v1: 3625.83,187.48 4395.6,187.48 590.55,188.87 1349.37,188.87 2108.19,188.87 2867.01,188.87 3625.83,231.85 590.55,233.24 1349.37,233.24 2108.19,233.24 2867.01,233.24 3625.83,275.42 4395.6,275.42 590.55,276.81 1349.37,276.81 2108.19,276.81 2867.01,276.81 5039.37,296.43 5076.57,335.12
+15V_1: C1.1 C4.1 C5.1 C6.1 C9.1 D1.3 J1.1 R1.2 R2.2 | length 2400.9
  Top Layer w50: R2.2@620.6,1440.79 689.1,1440.79 R1.2@698.94,1430.94
  Top Layer w55: C4.1@364.3,1333.78 C5.1@669.42,1333.78
  Top Layer w60: C6.1@515.87,1411.89 515.87,1398.11 ; 521.78,1363.31 521.78,1392.2 ; R1.2@698.94,1430.94 679.89,1411.89 ; C5.1@709.18,1325.98 R1.2@709.18,1440.79 ; 515.87,1398.11 529.65,1411.89 679.89,1411.89 ; 515.87,1398.11 521.78,1392.2 ; 521.78,1392.2 550.68,1363.31 698.94,1363.31 680.68,1381.57 v1(688.98,1381.57) 688.98,1401.29 679.13,1411.13 679.26,1411.26 679.89,1411.89
  Bottom Layer w70: 669.88,1372.52 660.83,1381.57 v1(639.76,1381.57) 599.73,1381.57 v1(590.68,1372.52) 337.72,1372.52 246.19,1464.06 246.19,1848.02 312.17,1914 J1.1@758.63,1914
  other v1: 236.35,1618.58 236.35,1670.1 236.35,1722.02
+15V_2: C1_1.1 C4_1.1 C5_1.1 C6_1.1 C9_1.1 D1_1.3 J1_1.1 R1_1.2 R2_1.2 | length 2400.9
  Top Layer w50: R2_1.2@1380.6,1440.79 1449.1,1440.79 R1_1.2@1458.94,1430.94
  Top Layer w55: C4_1.1@1124.3,1333.78 C5_1.1@1429.42,1333.78
  Top Layer w60: C6_1.1@1275.87,1411.89 1275.87,1398.11 ; 1281.78,1363.31 1281.78,1392.2 ; R1_1.2@1458.94,1430.94 1439.89,1411.89 ; C5_1.1@1469.18,1325.98 R1_1.2@1469.18,1440.79 ; 1275.87,1398.11 1281.78,1392.2 ; 1275.87,1398.11 1289.65,1411.89 1439.89,1411.89 ; 1281.78,1392.2 1310.68,1363.31 1458.94,1363.31 1440.68,1381.57 v1(1448.98,1381.57) 1448.98,1401.29 1439.13,1411.13 1439.26,1411.26 1439.89,1411.89
  Bottom Layer w70: 1429.88,1372.52 1420.83,1381.57 v1(1399.76,1381.57) 1359.73,1381.57 v1(1350.68,1372.52) 1097.72,1372.52 1006.19,1464.06 1006.19,1848.02 1072.17,1914 J1_1.1@1518.63,1914
  other v1: 996.35,1618.58 996.35,1670.1 996.35,1722.02
+15V_3: C1_2.1 C4_2.1 C5_2.1 C6_2.1 C9_2.1 D1_2.3 J1_2.1 R1_2.2 R2_2.2 | length 2400.9
  Top Layer w50: R2_2.2@2140.6,1440.79 2209.1,1440.79 R1_2.2@2218.94,1430.94
  Top Layer w55: C4_2.1@1884.3,1333.78 C5_2.1@2189.42,1333.78
  Top Layer w60: C6_2.1@2035.87,1411.89 2035.87,1398.11 ; 2041.78,1363.31 2041.78,1392.2 ; R1_2.2@2218.94,1430.94 2199.89,1411.89 ; C5_2.1@2229.18,1325.98 R1_2.2@2229.18,1440.79 ; 2035.87,1398.11 2041.78,1392.2 ; 2035.87,1398.11 2049.65,1411.89 2199.89,1411.89 ; 2041.78,1392.2 2070.68,1363.31 2218.94,1363.31 2200.68,1381.57 v1(2208.98,1381.57) 2208.98,1401.29 2199.13,1411.13 2199.26,1411.26 2199.89,1411.89
  Bottom Layer w70: 2189.88,1372.52 2180.83,1381.57 v1(2159.76,1381.57) 2119.73,1381.57 v1(2110.68,1372.52) 1857.72,1372.52 1766.19,1464.06 1766.19,1848.02 1832.17,1914 J1_2.1@2278.63,1914
  other v1: 1756.35,1618.58 1756.35,1670.1 1756.35,1722.02
+15V_4: C1_3.1 C4_3.1 C5_3.1 C6_3.1 C9_3.1 D1_3.3 J1_3.1 R1_3.2 R2_3.2 | length 2400.9
  Top Layer w50: R2_3.2@2900.6,1440.79 2969.1,1440.79 R1_3.2@2978.94,1430.94
  Top Layer w55: C4_3.1@2644.3,1333.78 C5_3.1@2949.42,1333.78
  Top Layer w60: C6_3.1@2795.87,1411.89 2795.87,1398.11 ; 2801.78,1363.31 2801.78,1392.2 ; R1_3.2@2978.94,1430.94 2959.89,1411.89 ; C5_3.1@2989.18,1325.98 R1_3.2@2989.18,1440.79 ; 2795.87,1398.11 2801.78,1392.2 ; 2795.87,1398.11 2809.65,1411.89 2959.89,1411.89 ; 2801.78,1392.2 2830.68,1363.31 2978.94,1363.31 2960.68,1381.57 v1(2968.98,1381.57) 2968.98,1401.29 2959.13,1411.13 2959.26,1411.26 2959.89,1411.89
  Bottom Layer w70: 2949.88,1372.52 2940.83,1381.57 v1(2919.76,1381.57) 2879.73,1381.57 v1(2870.68,1372.52) 2617.72,1372.52 2526.19,1464.06 2526.19,1848.02 2592.17,1914 J1_3.1@3038.63,1914
  other v1: 2516.35,1618.58 2516.35,1670.1 2516.35,1722.02
+15V_5: C1_4.1 C4_4.1 C5_4.1 C6_4.1 C9_4.1 D1_4.3 J1_4.1 R1_4.2 R2_4.2 | length 2400.9
  Top Layer w50: R2_4.2@3660.6,1440.79 3729.1,1440.79 R1_4.2@3738.94,1430.94
  Top Layer w55: C4_4.1@3404.3,1333.78 C5_4.1@3709.42,1333.78
  Top Layer w60: C6_4.1@3555.87,1411.89 3555.87,1398.11 ; 3561.78,1363.31 3561.78,1392.2 ; R1_4.2@3738.94,1430.94 3719.89,1411.89 ; C5_4.1@3749.18,1325.98 R1_4.2@3749.18,1440.79 ; 3555.87,1398.11 3561.78,1392.2 ; 3555.87,1398.11 3569.65,1411.89 3719.89,1411.89 ; 3561.78,1392.2 3590.68,1363.31 3738.94,1363.31 3720.68,1381.57 v1(3728.98,1381.57) 3728.98,1401.29 3719.13,1411.13 3719.26,1411.26 3719.89,1411.89
  Bottom Layer w70: 3709.88,1372.52 3700.83,1381.57 v1(3679.76,1381.57) 3639.73,1381.57 v1(3630.68,1372.52) 3377.72,1372.52 3286.19,1464.06 3286.19,1848.02 3352.17,1914 J1_4.1@3798.63,1914
  other v1: 3276.35,1618.58 3276.35,1670.1 3276.35,1722.02
+15V_6: C1_5.1 C4_5.1 C5_5.1 C6_5.1 C9_5.1 D1_5.3 J1_5.1 R1_5.2 R2_5.2 | length 2400.9
  Top Layer w50: R2_5.2@4420.6,1440.79 4489.1,1440.79 R1_5.2@4498.94,1430.94
  Top Layer w55: C4_5.1@4164.3,1333.78 C5_5.1@4469.42,1333.78
  Top Layer w60: C6_5.1@4315.87,1411.89 4315.87,1398.11 ; 4321.78,1363.31 4321.78,1392.2 ; R1_5.2@4498.94,1430.94 4479.89,1411.89 ; C5_5.1@4509.18,1325.98 R1_5.2@4509.18,1440.79 ; 4315.87,1398.11 4321.78,1392.2 ; 4315.87,1398.11 4329.65,1411.89 4479.89,1411.89 ; 4321.78,1392.2 4350.68,1363.31 4498.94,1363.31 4480.68,1381.57 v1(4488.98,1381.57) 4488.98,1401.29 4479.13,1411.13 4479.26,1411.26 4479.89,1411.89
  Bottom Layer w70: 4469.88,1372.52 4460.83,1381.57 v1(4439.76,1381.57) 4399.73,1381.57 v1(4390.68,1372.52) 4137.72,1372.52 4046.19,1464.06 4046.19,1848.02 4112.17,1914 J1_5.1@4558.63,1914
  other v1: 4036.35,1618.58 4036.35,1670.1 4036.35,1722.02
-4V_1: C4.2 C5.2 C6.2 C7.2 C10.2 D2.1 J1.3 R4.1 T1.5 U2.3 | length 2935.9
  Top Layer w40: C6.2@434.67,1430.1 C6.2@443.04,1421.73 ; C10.2@482.41,1654.55 594.08,1654.55 620.6,1628.03 D2.1@620.6,1617.15 ; v1(738.32,1165.83) 780.95,1208.46 780.95,1273.31 ; 738.32,1234.72 742.36,1234.72 780.95,1273.31 ; J1.3@758.63,1714 780.95,1691.68 780.95,1273.31
  Top Layer w50: C6.2@426.31,1421.73 431.33,1426.75 R4.1@431.33,1508.35 ; T1.5@510.26,1089.84 510.26,1118.29 ; 510.26,1118.29 v1(482.41,1146.14) v1(531.62,1146.14) 510.26,1124.78 510.26,1118.29
  Top Layer w55: 285.56,1222.91 v1(285.56,1165.83) v1(285.56,1116.61) 285.56,1087.09 ; 334.77,1219.78 v1(334.77,1165.83) v1(334.77,1116.61) 334.77,1089.84 332.02,1087.09 285.56,1087.09 ; C4.2@364.3,1253.78 v1@256.03,1253.78 ; C6.2@426.31,1421.73 263.12,1421.73 256.03,1414.65 v1@256.03,1253.78 ; v1@256.03,1253.78 256.03,1106.77 275.72,1087.09 285.56,1087.09 ; 689.1,1096.93 v1(689.1,1116.61) v1(689.1,1165.83) 689.1,1234.72 738.32,1234.72 v1(738.32,1165.83) v1(738.32,1116.61) 738.32,1099.69 725.72,1087.09 698.94,1087.09 689.1,1096.93
  Bottom Layer w70: v1(738.32,1165.83) 767.84,1195.35 767.84,1704.79 J1.3@758.63,1714
  other v1: 256.03,1264.25 256.03,1313.46 559.18,1722.02 610.76,1722.02
-4V_2: C4_1.2 C5_1.2 C6_1.2 C7_1.2 C10_1.2 D2_1.1 J1_1.3 R4_1.1 T1_1.5 U2_1.3 | length 2935.9
  Top Layer w40: C6_1.2@1194.67,1430.1 C6_1.2@1203.04,1421.73 ; C10_1.2@1242.41,1654.55 1354.08,1654.55 1380.6,1628.03 D2_1.1@1380.6,1617.15 ; v1(1498.32,1165.83) 1540.95,1208.46 1540.95,1273.31 ; 1498.32,1234.72 1502.36,1234.72 1540.95,1273.31 ; J1_1.3@1518.63,1714 1540.95,1691.68 1540.95,1273.31
  Top Layer w50: C6_1.2@1186.31,1421.73 1191.33,1426.75 R4_1.1@1191.33,1508.35 ; T1_1.5@1270.26,1089.84 1270.26,1118.29 ; 1270.26,1118.29 1270.26,1124.78 v1(1291.62,1146.14) v1(1242.41,1146.14) 1270.26,1118.29
  Top Layer w55: 1045.56,1222.91 v1(1045.56,1165.83) v1(1045.56,1116.61) 1045.56,1087.09 ; 1094.77,1219.78 v1(1094.77,1165.83) v1(1094.77,1116.61) 1094.77,1089.84 1092.02,1087.09 1045.56,1087.09 ; C4_1.2@1124.3,1253.78 v1@1016.03,1253.78 ; C6_1.2@1186.31,1421.73 1023.12,1421.73 1016.03,1414.65 v1@1016.03,1253.78 ; v1@1016.03,1253.78 1016.03,1106.77 1035.72,1087.09 1045.56,1087.09 ; 1449.1,1096.93 1458.94,1087.09 1485.72,1087.09 1498.32,1099.69 v1(1498.32,1116.61) v1(1498.32,1165.83) 1498.32,1234.72 1449.1,1234.72 v1(1449.1,1165.83) v1(1449.1,1116.61) 1449.1,1096.93
  Bottom Layer w70: v1(1498.32,1165.83) 1527.84,1195.35 1527.84,1704.79 J1_1.3@1518.63,1714
  other v1: 1016.03,1264.25 1016.03,1313.46 1319.18,1722.02 1370.76,1722.02
-4V_3: C4_2.2 C5_2.2 C6_2.2 C7_2.2 C10_2.2 D2_2.1 J1_2.3 R4_2.1 T1_2.5 U2_2.3 | length 2935.9
  Top Layer w40: C6_2.2@1954.67,1430.1 C6_2.2@1963.04,1421.73 ; C10_2.2@2002.41,1654.55 2114.08,1654.55 2140.6,1628.03 D2_2.1@2140.6,1617.15 ; v1(2258.32,1165.83) 2300.95,1208.46 2300.95,1273.31 ; 2258.32,1234.72 2262.36,1234.72 2300.95,1273.31 ; J1_2.3@2278.63,1714 2300.95,1691.68 2300.95,1273.31
  Top Layer w50: C6_2.2@1946.31,1421.73 1951.33,1426.75 R4_2.1@1951.33,1508.35 ; T1_2.5@2030.26,1089.84 2030.26,1118.29 ; 2030.26,1118.29 2030.26,1124.78 v1(2051.62,1146.14) v1(2002.41,1146.14) 2030.26,1118.29
  Top Layer w55: 1805.56,1222.91 v1(1805.56,1165.83) v1(1805.56,1116.61) 1805.56,1087.09 ; 1854.77,1219.78 v1(1854.77,1165.83) v1(1854.77,1116.61) 1854.77,1089.84 1852.02,1087.09 1805.56,1087.09 ; C4_2.2@1884.3,1253.78 v1@1776.03,1253.78 ; C6_2.2@1946.31,1421.73 1783.12,1421.73 1776.03,1414.65 v1@1776.03,1253.78 ; v1@1776.03,1253.78 1776.03,1106.77 1795.72,1087.09 1805.56,1087.09 ; 2209.1,1096.93 2218.94,1087.09 2245.72,1087.09 2258.32,1099.69 v1(2258.32,1116.61) v1(2258.32,1165.83) 2258.32,1234.72 2209.1,1234.72 v1(2209.1,1165.83) v1(2209.1,1116.61) 2209.1,1096.93
  Bottom Layer w70: v1(2258.32,1165.83) 2287.84,1195.35 2287.84,1704.79 J1_2.3@2278.63,1714
  other v1: 1776.03,1264.25 1776.03,1313.46 2079.18,1722.02 2130.76,1722.02
-4V_4: C4_3.2 C5_3.2 C6_3.2 C7_3.2 C10_3.2 D2_3.1 J1_3.3 R4_3.1 T1_3.5 U2_3.3 | length 2935.9
  Top Layer w40: C6_3.2@2714.67,1430.1 C6_3.2@2723.04,1421.73 ; C10_3.2@2762.41,1654.55 2874.08,1654.55 2900.6,1628.03 D2_3.1@2900.6,1617.15 ; v1(3018.32,1165.83) 3060.95,1208.46 3060.95,1273.31 ; 3018.32,1234.72 3022.36,1234.72 3060.95,1273.31 ; J1_3.3@3038.63,1714 3060.95,1691.68 3060.95,1273.31
  Top Layer w50: C6_3.2@2706.31,1421.73 2711.33,1426.75 R4_3.1@2711.33,1508.35 ; T1_3.5@2790.26,1089.84 2790.26,1118.29 ; 2790.26,1118.29 2790.26,1124.78 v1(2811.62,1146.14) v1(2762.41,1146.14) 2790.26,1118.29
  Top Layer w55: 2565.56,1222.91 v1(2565.56,1165.83) v1(2565.56,1116.61) 2565.56,1087.09 ; 2614.77,1219.78 v1(2614.77,1165.83) v1(2614.77,1116.61) 2614.77,1089.84 2612.02,1087.09 2565.56,1087.09 ; C4_3.2@2644.3,1253.78 v1@2536.03,1253.78 ; C6_3.2@2706.31,1421.73 2543.12,1421.73 2536.03,1414.65 v1@2536.03,1253.78 ; v1@2536.03,1253.78 2536.03,1106.77 2555.72,1087.09 2565.56,1087.09 ; 2969.1,1096.93 2978.94,1087.09 3005.72,1087.09 3018.32,1099.69 v1(3018.32,1116.61) v1(3018.32,1165.83) 3018.32,1234.72 2969.1,1234.72 v1(2969.1,1165.83) v1(2969.1,1116.61) 2969.1,1096.93
  Bottom Layer w70: v1(3018.32,1165.83) 3047.84,1195.35 3047.84,1704.79 J1_3.3@3038.63,1714
  other v1: 2536.03,1264.25 2536.03,1313.46 2839.18,1722.02 2890.76,1722.02
-4V_5: C4_4.2 C5_4.2 C6_4.2 C7_4.2 C10_4.2 D2_4.1 J1_4.3 R4_4.1 T1_4.5 U2_4.3 | length 2935.9
  Top Layer w40: C6_4.2@3474.67,1430.1 C6_4.2@3483.04,1421.73 ; C10_4.2@3522.41,1654.55 3634.08,1654.55 3660.6,1628.03 D2_4.1@3660.6,1617.15 ; v1(3778.31,1165.83) 3820.95,1208.46 3820.95,1273.31 ; 3778.31,1234.72 3782.36,1234.72 3820.95,1273.31 ; J1_4.3@3798.63,1714 3820.95,1691.68 3820.95,1273.31
  Top Layer w50: C6_4.2@3466.31,1421.73 3471.33,1426.75 R4_4.1@3471.33,1508.35 ; T1_4.5@3550.26,1089.84 3550.26,1118.29 ; 3550.26,1118.29 3550.26,1124.78 v1(3571.62,1146.14) v1(3522.41,1146.14) 3550.26,1118.29
  Top Layer w55: 3325.56,1222.91 v1(3325.56,1165.83) v1(3325.56,1116.61) 3325.56,1087.09 ; 3374.77,1219.78 v1(3374.77,1165.83) v1(3374.77,1116.61) 3374.77,1089.84 3372.02,1087.09 3325.56,1087.09 ; C4_4.2@3404.3,1253.78 v1@3296.03,1253.78 ; C6_4.2@3466.31,1421.73 3303.12,1421.73 3296.03,1414.65 v1@3296.03,1253.78 ; v1@3296.03,1253.78 3296.03,1106.77 3315.72,1087.09 3325.56,1087.09 ; 3729.1,1096.93 3738.94,1087.09 3765.72,1087.09 3778.31,1099.69 v1(3778.31,1116.61) v1(3778.31,1165.83) 3778.31,1234.72 3729.1,1234.72 v1(3729.1,1165.83) v1(3729.1,1116.61) 3729.1,1096.93
  Bottom Layer w70: v1(3778.31,1165.83) 3807.84,1195.35 3807.84,1704.79 J1_4.3@3798.63,1714
  other v1: 3296.03,1264.25 3296.03,1313.46 3599.18,1722.02 3650.76,1722.02
-4V_6: C4_5.2 C5_5.2 C6_5.2 C7_5.2 C10_5.2 D2_5.1 J1_5.3 R4_5.1 T1_5.5 U2_5.3 | length 2935.9
  Top Layer w40: C6_5.2@4234.67,1430.1 C6_5.2@4243.04,1421.73 ; C10_5.2@4282.41,1654.55 4394.08,1654.55 4420.6,1628.03 D2_5.1@4420.6,1617.15 ; v1(4538.31,1165.83) 4580.95,1208.46 4580.95,1273.31 ; 4538.31,1234.72 4542.36,1234.72 4580.95,1273.31 ; J1_5.3@4558.63,1714 4580.95,1691.68 4580.95,1273.31
  Top Layer w50: C6_5.2@4226.31,1421.73 4231.33,1426.75 R4_5.1@4231.33,1508.35 ; T1_5.5@4310.26,1089.84 4310.26,1118.29 ; 4310.26,1118.29 4310.26,1124.78 v1(4331.62,1146.14) v1(4282.41,1146.14) 4310.26,1118.29
  Top Layer w55: 4085.56,1222.91 v1(4085.56,1165.83) v1(4085.56,1116.61) 4085.56,1087.09 ; 4134.77,1219.78 v1(4134.77,1165.83) v1(4134.77,1116.61) 4134.77,1089.84 4132.02,1087.09 4085.56,1087.09 ; C4_5.2@4164.3,1253.78 v1@4056.03,1253.78 ; C6_5.2@4226.31,1421.73 4063.12,1421.73 4056.03,1414.65 v1@4056.03,1253.78 ; v1@4056.03,1253.78 4056.03,1106.77 4075.72,1087.09 4085.56,1087.09 ; 4489.1,1096.93 4498.94,1087.09 4525.72,1087.09 4538.31,1099.69 v1(4538.31,1116.61) v1(4538.31,1165.83) 4538.31,1234.72 4489.1,1234.72 v1(4489.1,1165.83) v1(4489.1,1116.61) 4489.1,1096.93
  Bottom Layer w70: v1(4538.31,1165.83) 4567.84,1195.35 4567.84,1704.79 J1_5.3@4558.63,1714
  other v1: 4056.03,1264.25 4056.03,1313.46 4359.18,1722.02 4410.76,1722.02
